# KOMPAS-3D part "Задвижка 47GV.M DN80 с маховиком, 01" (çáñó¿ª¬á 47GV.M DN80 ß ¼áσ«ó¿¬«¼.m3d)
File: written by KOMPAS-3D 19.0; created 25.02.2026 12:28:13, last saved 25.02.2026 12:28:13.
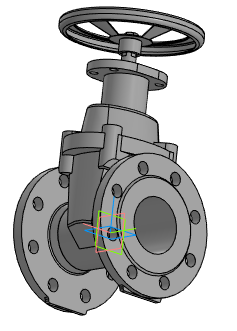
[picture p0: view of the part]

Document properties: Автор: Энергия; Полное имя файла: ..\..\47GVM\DR.47GVM.080.16.00.000\DR.47GVM.080.16.00.00 - Задвижка с обрезиненным клином DN80.a3d

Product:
- Part/product: Задвижка 47GV.M DN80 с маховиком  | designation 01
    Масса: 15.8677
  - Component [detail]: Шпиндель  | pos. 5  | Материал: Сталь 20Х13 ГОСТ 5632 - 2014 (density 7670 kg/m3); Масса: 0.555362; Раздел спецификации: Детали; Форматы листов документа: A3; source file: 47GV.M DN80\DR.47GVM.080.16.00.003 - Шпиндель.cdw, 47GV.M DN80\DR.47GVM.080.16.00.003 - Шпиндель.m3d
  - Component [assembly]: Клин с направляющими  | designation DR.47GVM.080.16.01.000  | pos. 4  | Масса: 2.00985; Раздел спецификации: Сборочные единицы; Форматы листов документа: A4; source file: 47GV.M DN80\DR.47GVM.080.16.01.000 - Клин с направляющими.a3d, 47GV.M DN80\DR.47GVM.080.16.01.000 - Клин с направляющими.spw, 47GV.M DN80\DR.47GVM.080.16.01.000 СБ - Клин с направляющими.cdw
  - Component [detail]: Корпус DN80  | pos. 3  | Материал: ВЧ50 ГОСТ 7293-85 (density 7200 kg/m3); Масса: 9.71692; Раздел спецификации: Детали; Форматы листов документа: 2xA3; source file: 47GV.M DN80\DR.47GVM.050.16.00.001 - Корпус.cdw, 47GV.M DN80\DR.47GVM.080.16.00.001 - Корпус.cdw, 47GV.M DN80\DR.47GVM.080.16.00.001 - Корпус.m3d
  - Component [detail]: Крышка DN80  | pos. 4  | Материал: ВЧ50 ГОСТ 7293-85 (density 7200 kg/m3); Масса: 2.81145; Раздел спецификации: Детали; Форматы листов документа: 2xA3; source file: 47GV.M DN80\DR.47GVM.080.16.00.002 - Крышка.cdw, 47GV.M DN80\DR.47GVM.080.16.00.002 - Крышка.m3d
  - Component [detail]: Маховик 200  | pos. 15  | Масса: 0.448137; Раздел спецификации: Прочие изделия; source file: 47GV.M DN80\Маховик 200.m3d
  - Component [standard]: Шайба1021695878  | pos. 20  | Материал: Сталь 12Х18Н10Т ГОСТ 5632-2014 (density 1000 kg/m3); Масса: 0.0121728; Раздел спецификации: Стандартные изделия; Рассекать на разрезах: no; additional columns: ГОСТ 6958-78; A 10.21
  - Component [standard]: Болт М10-6gx20-А2-70 ГОСТ 7798-70  | pos. 12  | Масса: 0.02379; Раздел спецификации: Стандартные изделия; Рассекать на разрезах: no
- Part/product: Задвижка 47GV.M DN80 с маховиком
    Масса: 20.2492
    source file: 47GV.M DN80\DR.47GVM.080.16.00.00 - Задвижка с обрезиненным клином DN80.spw
  - Component: Задвижка с обрезиненным клином DN80. Сборочный чертеж  | designation DR.47GVM.080.16.00.00СБ  | pos. 0  | Масса: 15.8764; Раздел спецификации: Документация; Форматы листов документа: 2xA3; source file: 47GV.M DN80\DR.47GVM.080.16.00.000 СБ - Задвижка с обрезиненным клином DN80.cdw

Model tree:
1. Операция без истории:1

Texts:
  Точка начала. Х
  Точка начала. Y
  Точка начала. Z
